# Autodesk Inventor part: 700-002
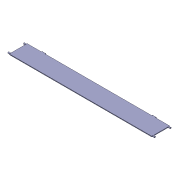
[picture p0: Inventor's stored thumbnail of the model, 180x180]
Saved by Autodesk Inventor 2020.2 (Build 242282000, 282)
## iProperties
Created: 2018-01
Part Number: 700-002
Material: Ogólne
Document SubType Name: Modeling
Designer: F.Stasiak
Density: 1 g/cm^3
Appearance: Szaroniebieska
Manager: www.cadconsulting.pl
Company: Fabian Stasiak CAD Consulting
Author: F.Stasiak
Subject: Zbiór ćwiczeń. Autodesk Inventor 2020. Kurs podstawowy
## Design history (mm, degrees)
sketch "Szkic1"
  geometry: L1 (2000, -250)-(-2000, -250); L2 (-2000, -250)-(-2000, 250); L3 (-2000, 250)-(2000, 250); L4 (2000, 250)-(2000, -250); L5 (2000, -250)-(-2000, 250); L6 (-2000, -250)-(2000, 250); 1 further point
  constraints: 12 end point, 2 midpoint, 2 parallel, 1 horizontal, 1 perpendicular
  dimensions: "d0" = 4000 distance of L2.end L3.end; "d1" = 500 distance of L1.end L2.end
extrude "Wyciągnięcie proste1" new body sketch "Szkic1" stored distance "d2" = 20; taper "d3" = 0 deg
sketch "Szkic4"
  geometry: L1 (2000, 250)-(-2000, 250) reference; L2 (-1600, 250)-(-1600, 268); L3 (-1600, 268)-(-1500, 268); L4 (-1500, 268)-(-1500, 250); L5 (-2000, 250)-(-2000, -250) reference; 1 further point
  constraints: 6 end point, 2 perpendicular, 2 point on line, 1 vertical
  dimensions: "d13" = 18 distance between parallel lines of L3 L1; "d26" = 100 distance of L2.end L3.end; "d27" = 400 distance between parallel lines of L5 L2
extrude "Wyciągnięcie proste4" join sketch "Szkic4" distance "d14" = 20; taper "d15" = 0 deg
sketch "Szkic5"
  geometry: L1 (0, 18)-(20, 18) reference; C1 r 10 at (10, 18); 1 further point
  constraints: 1 centre point, 1 midpoint
  dimensions: "d16" = 20 diameter of C1
extrude "Wyciągnięcie proste5" join sketch "Szkic5" stored distance "d17" = 10; taper "d18" = 0 deg
sketch "Szkic6"
  geometry: C1 r 5.5 at (10, 18); 6 further points
  constraints: 1 centre point, 1 coincident, 1 other
  dimensions: "d19" = 11 diameter of C1
extrude "Wyciągnięcie proste6" cut sketch "Szkic6" extent not by distance; stored distance "d20" = 10; taper "d21" = 0 deg
sketch "Szkic7"
  geometry: L1 (20, 0)-(0, 0) reference; C1 r 20 at (10, 30); 1 further point
  constraints: 1 centre point, 1 midpoint, 1 vertical alignment
  dimensions: "d22" = 40 diameter of C1; "d25" = 30 distance from line of L1 C1.centre
extrude "Wyciągnięcie proste7" join sketch "Szkic7" distance "d23" = 55; taper "d24" = 0 deg
mirror "Odbij2"
mirror "Odbij1"
node "Bryła1"
